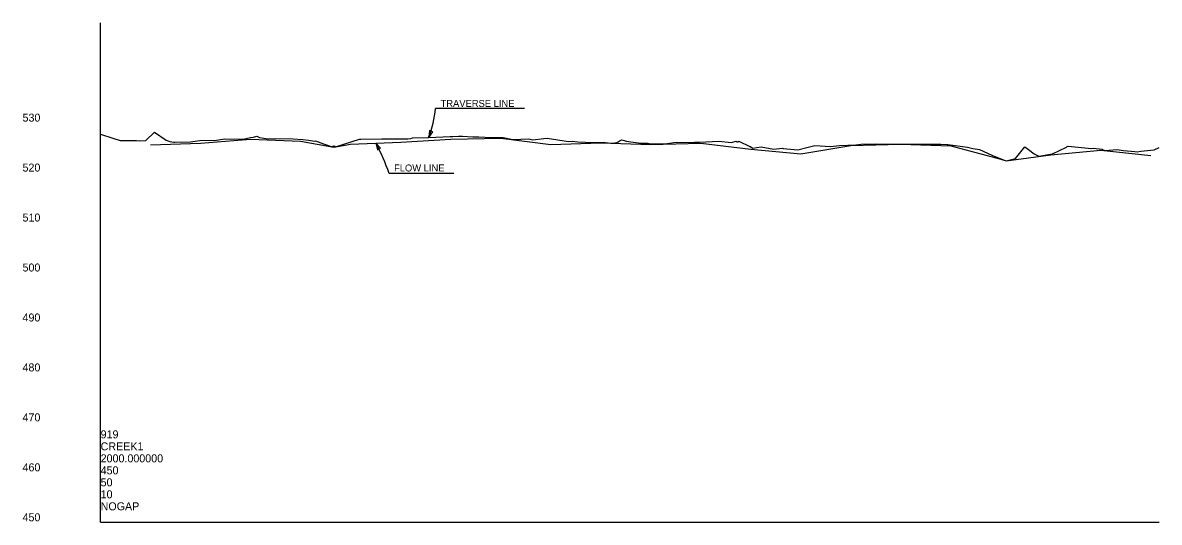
# Model space of a CAD drawing. Extents: x 49922 to 52614, y 49991 to 60509.
# Drawn here: x 49922 to 51059, y 55000 to 55500 of the extents above; entities that cross this region are included whole.
import ezdxf

# ---------------------------------------------------------------- set-up
doc = ezdxf.new("R2010")
doc.units = 0
for name, color, linetype in [('RD_DDB_ElevTX', 7, 'Continuous'), ('RD_DDB_Profile_EX', 7, 'Continuous'), ('RD_GPK_Profile_Cell', 7, 'Continuous'), ('RD_TX_Profile', 7, 'Continuous')]:
    doc.layers.add(name, color=color, linetype=linetype)

msp = doc.modelspace()

# ---------------------------------------------------------------- linework, layer by layer
at = {"layer": 'RD_DDB_Profile_EX'}
for points in [[(50000, 55388.6), (50012.2, 55384.3), (50019.6, 55382.2), (50020.8, 55382), (50036, 55382.2), (50038.4, 55381.8), (50045.2, 55382.2), (50053.9, 55390.4), (50065.5, 55382.5), (50069.3, 55381.2), (50073.3, 55380.3), (50074.3, 55380.4), (50089.9, 55380.9), (50099.1, 55382.1), (50115.7, 55382.6), (50124, 55383.7), (50138, 55383.5), (50142.5, 55383.6), (50149.9, 55385.1), (50152.9, 55385.3), (50156.1, 55386.4), (50158.9, 55385.1), (50167.5, 55383.7), (50174.9, 55384), (50192.5, 55383.7), (50202.1, 55383.2), (50207.7, 55382.4), (50213.8, 55381.6), (50214.8, 55381.8), (50223, 55378.8), (50231.6, 55375.9), (50232, 55376.4), (50233.2, 55376.9), (50234.1, 55376.4), (50234.7, 55375.9), (50258.9, 55383.6), (50259.4, 55383.6), (50260.2, 55383.6), (50281.2, 55383.7), (50285.1, 55383.9), (50307.2, 55383.9), (50310, 55384), (50311.7, 55384.7), (50328, 55385.2), (50349.5, 55386.2), (50352, 55386.1), (50357.7, 55386.5), (50359.6, 55386.6), (50361.7, 55386.5), (50372, 55385.7), (50378.2, 55385.7), (50390.6, 55385.1), (50402.6, 55385.1), (50412.1, 55383), (50428.1, 55383.8), (50432.3, 55382.9), (50443.1, 55384), (50446.4, 55384.4), (50467.9, 55381.1), (50471.4, 55381.6), (50477.1, 55380.9), (50492.4, 55380), (50502.5, 55380.3), (50507.6, 55379.7), (50511.4, 55379.5), (50514, 55379.9), (50516.3, 55380.2), (50517.4, 55380.7), (50519.6, 55382.2), (50520.8, 55382.9), (50522.3, 55382.6), (50525.8, 55381.4), (50527.8, 55381), (50540, 55379.3), (50546.9, 55379.5), (50550.6, 55378.9), (50566.6, 55379.2), (50575.5, 55380.6), (50590.9, 55380.2), (50593.7, 55380.5), (50598.7, 55380.3), (50618.2, 55381.5), (50630.4, 55380.2), (50635.5, 55381.6), (50636.6, 55380.9), (50637.5, 55380.9), (50638, 55381.4), (50649.2, 55376.2), (50649.7, 55376), (50651.9, 55374.3), (50660.4, 55375.8), (50673.1, 55373.3), (50681.3, 55374.5), (50682.6, 55374.2), (50697.2, 55372.9), (50707.5, 55375.5), (50714, 55377.1), (50729.8, 55376.2), (50738.7, 55377.2), (50755.1, 55377.7), (50760.4, 55378.3)], [(50050, 55377.8), (50100, 55379.3), (50150, 55383.4), (50200, 55381.5), (50233.1, 55375.5), (50250, 55378.4), (50300, 55380.6), (50350, 55383.5), (50400, 55384.3), (50450, 55378), (50500, 55379.9), (50550, 55378.1), (50600, 55379.3), (50650, 55373.3), (50700, 55368.8), (50750, 55377), (50800, 55378.4), (50850, 55376.9), (50900, 55363.4), (50905.3, 55361.7), (50950, 55367.9), (51000, 55372.6), (51050, 55367.1)], [(50760.4, 55378.3), (50775.3, 55378.7), (50779.1, 55378.5), (50800.2, 55378.5), (50804.9, 55378.3), (50825.2, 55378.3), (50840.2, 55378.3), (50846.3, 55378.1), (50847, 55378), (50866.8, 55375.3), (50872, 55374.1), (50876.6, 55373.5), (50878.7, 55373), (50891.1, 55367.5), (50903.5, 55362.4), (50905.3, 55361.7), (50914.7, 55364.2), (50924, 55375.8), (50927.9, 55373.2), (50933.3, 55368.6), (50938, 55366.3), (50951.6, 55368.9), (50965.9, 55375.6), (50966.3, 55376.1), (50967.3, 55376.3), (50990.9, 55374.1), (50992.4, 55374.3), (51001.4, 55373.6), (51002.4, 55372.7), (51004.6, 55372.1), (51016, 55373.2), (51022.7, 55372.1), (51034.1, 55371), (51036.4, 55370.8), (51040.1, 55371.3), (51053.4, 55372.8), (51058.5, 55375)]]:
    msp.add_lwpolyline(points, dxfattribs=at)
at = {"layer": 'RD_GPK_Profile_Cell'}
for q in [(50000, 55500), (51058.5, 55000), (50000, 55000)]:
    msp.add_line((50000, 55000), q, dxfattribs=at)
at = {"layer": 'RD_TX_Profile'}
for p, q in [((50423.7, 55414.2), (50334.9, 55414.2)), ((50353.3, 55349.1), (50288.4, 55349.1))]:
    msp.add_line(p, q, dxfattribs=at)
for points in [[(50328.7, 55392.1), (50328, 55385.2), (50332.1, 55390.8)], [(50279.9, 55374.5), (50275, 55379.5), (50276.7, 55372.7)]]:
    msp.add_lwpolyline(points, close=True, dxfattribs=at)
for centre, radius, start, end in [((50222.8, 55425.4), 112.6, 339.0695, 354.2828), ((50111.6, 55289.1), 186.8, 18.7278, 28.948)]:
    msp.add_arc(centre, radius, start, end, dxfattribs=at)

# ---------------------------------------------------------------- texts
at = {"layer": 'RD_DDB_ElevTX'}
for s, p in [('530', (49921.9, 55401)), ('520', (49921.9, 55351)), ('510', (49921.9, 55301)), ('500', (49921.9, 55251)), ('490', (49921.9, 55201)), ('480', (49921.9, 55151)), ('470', (49921.9, 55101)), ('460', (49921.9, 55051)), ('450', (49921.9, 55001))]:
    msp.add_text(s, height=8, dxfattribs=at).set_placement(p)
at = {"layer": 'RD_GPK_Profile_Cell'}
for s, p in [('919', (50000, 55084)), ('CREEK1', (50000, 55072)), ('2000.000000', (50000, 55060)), ('450', (50000, 55048)), ('50', (50000, 55036)), ('10', (50000, 55024)), ('NOGAP', (50000, 55012))]:
    msp.add_text(s, height=8, dxfattribs=at).set_placement(p)
at = {"layer": 'RD_TX_Profile'}
for s, p in [('TRAVERSE LINE', (50339.9, 55415.7)), ('FLOW LINE', (50293.4, 55351.1))]:
    msp.add_text(s, height=7, dxfattribs=at).set_placement(p)

doc.saveas('drawing.dxf')
